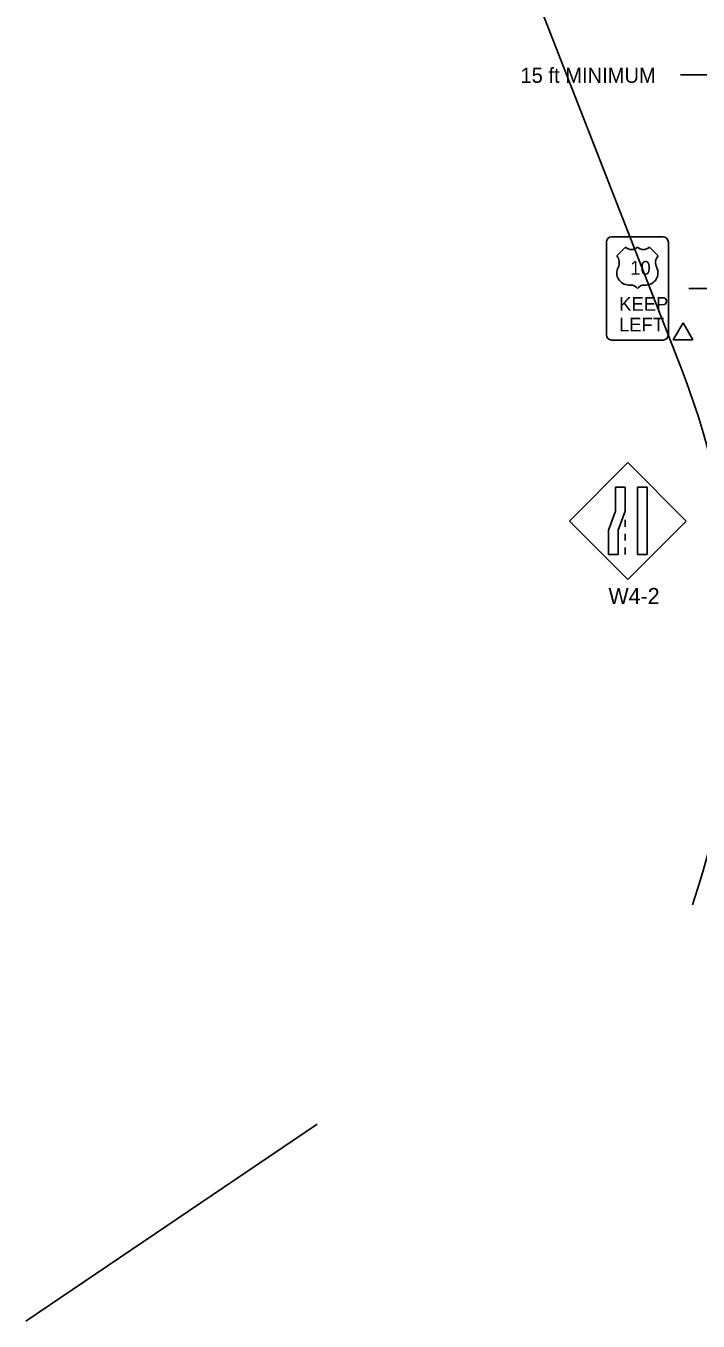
# Model space of a CAD drawing. Extents: x 16512 to 19504, y 5761 to 6984.
# Drawn here: x 16512 to 16825, y 5788 to 6391 of the extents above; entities that cross this region are included whole.
import ezdxf

# ---------------------------------------------------------------- set-up
doc = ezdxf.new("R2010")
doc.units = 0
for name, color, linetype in [('ALI_LEGAL_EX', 7, 'Continuous'), ('TRAFFIC_SIGNS_PR', 7, 'Continuous'), ('TYPICAL_EX', 7, 'Continuous'), ('TYPICAL_TEXT_DIMEN_PR', 7, 'Continuous')]:
    doc.layers.add(name, color=color, linetype=linetype)

msp = doc.modelspace()

# ---------------------------------------------------------------- linework, layer by layer
at = {"layer": 'ALI_LEGAL_EX'}
msp.add_line((16594.98, 6800.51), (16817, 6232.14), dxfattribs=at)
msp.add_arc((16477.95, 6099.7), 364, 341.14594, 21.33672, dxfattribs=at)
at = {"layer": 'TRAFFIC_SIGNS_PR'}
for p, q in [((16782.42, 6290.32), (16782.42, 6247.12)), ((16808.82, 6292.72), (16784.82, 6292.72)), ((16811.22, 6247.12), (16811.22, 6290.32)), ((16784.82, 6244.72), (16808.82, 6244.72)), ((16792.4, 6187.7), (16765.25, 6160.55)), ((16819.55, 6160.55), (16792.4, 6187.7)), ((16765.25, 6160.55), (16792.4, 6133.4)), ((16791.15, 6161.04), (16791.15, 6157.84)), ((16792.4, 6133.4), (16819.55, 6160.55)), ((16791.15, 6154.64), (16791.15, 6151.44)), ((16791.15, 6148.24), (16791.15, 6145.04))]:
    msp.add_line(p, q, dxfattribs=at)
for points in [[(16791.15, 6176.29), (16791.15, 6165.11), (16787.81, 6156.22), (16787.81, 6145.04), (16783.32, 6145.04), (16783.32, 6156.22), (16786.66, 6165.11), (16786.66, 6176.29)], [(16801.29, 6176.29), (16801.29, 6145.04), (16796.8, 6145.04), (16796.8, 6176.29)]]:
    msp.add_lwpolyline(points, close=True, dxfattribs=at)
for centre, start, end in [((16784.82, 6290.32), 90, 180), ((16808.82, 6290.32), 0, 90), ((16784.82, 6247.12), 180, 270), ((16808.82, 6247.12), 270, 0)]:
    msp.add_arc(centre, 2.4, start, end, dxfattribs=at)
at = {"layer": 'TYPICAL_EX'}
for p, q in [((16787.22, 6283.92), (16791.22, 6287.92)), ((16806.42, 6283.92), (16802.42, 6287.92)), ((16792.81, 6270.31), (16793.61, 6270.31)), ((16800.82, 6270.31), (16800.02, 6270.31))]:
    msp.add_line(p, q, dxfattribs=at)
for centre, radius, start, end in [((16783.43, 6280.72), 4.96, 333.09768, 40.19361), ((16794.02, 6290.84), 4.04, 226.14041, 313.85958), ((16799.62, 6290.84), 4.04, 226.14042, 313.85959), ((16810.21, 6280.72), 4.96, 139.80639, 206.90233), ((16792.82, 6275.91), 5.59, 152.6698, 269.90132), ((16800.81, 6275.91), 5.59, 270.09868, 27.3302), ((16793.62, 6266.31), 4.01, 37.1038, 90.13853), ((16800.01, 6266.31), 4.01, 89.86147, 142.8962)]:
    msp.add_arc(centre, radius, start, end, dxfattribs=at)
at = {"layer": 'TYPICAL_TEXT_DIMEN_PR'}
for p, q in [((16816.88, 6368.07), (16909.5, 6368.07)), ((16820.82, 6268.75), (16929.95, 6268.75)), ((16647.75, 5880), (16512.32, 5788.38))]:
    msp.add_line(p, q, dxfattribs=at)
msp.add_lwpolyline([(16818.04, 6252.68), (16813.51, 6244.85), (16822.56, 6244.85)], close=True, dxfattribs=at)

# ---------------------------------------------------------------- texts
at = {"layer": 'TRAFFIC_SIGNS_PR'}
for s, height, p in [('10', 6.4, (16793.48, 6275.12)), ('KEEP', 6.4, (16788.35, 6258.32)), ('LEFT', 6.4, (16788.27, 6248.72)), ('W4-2', 7.44, (16783.36, 6121.96))]:
    msp.add_text(s, height=height, dxfattribs=at).set_placement(p)
at = {"layer": 'TYPICAL_TEXT_DIMEN_PR'}
msp.add_text('15 ft MINIMUM', height=7, dxfattribs=at).set_placement((16742.42, 6364.37))

doc.saveas('drawing.dxf')
